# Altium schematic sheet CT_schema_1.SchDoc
size 500 x 441 mm
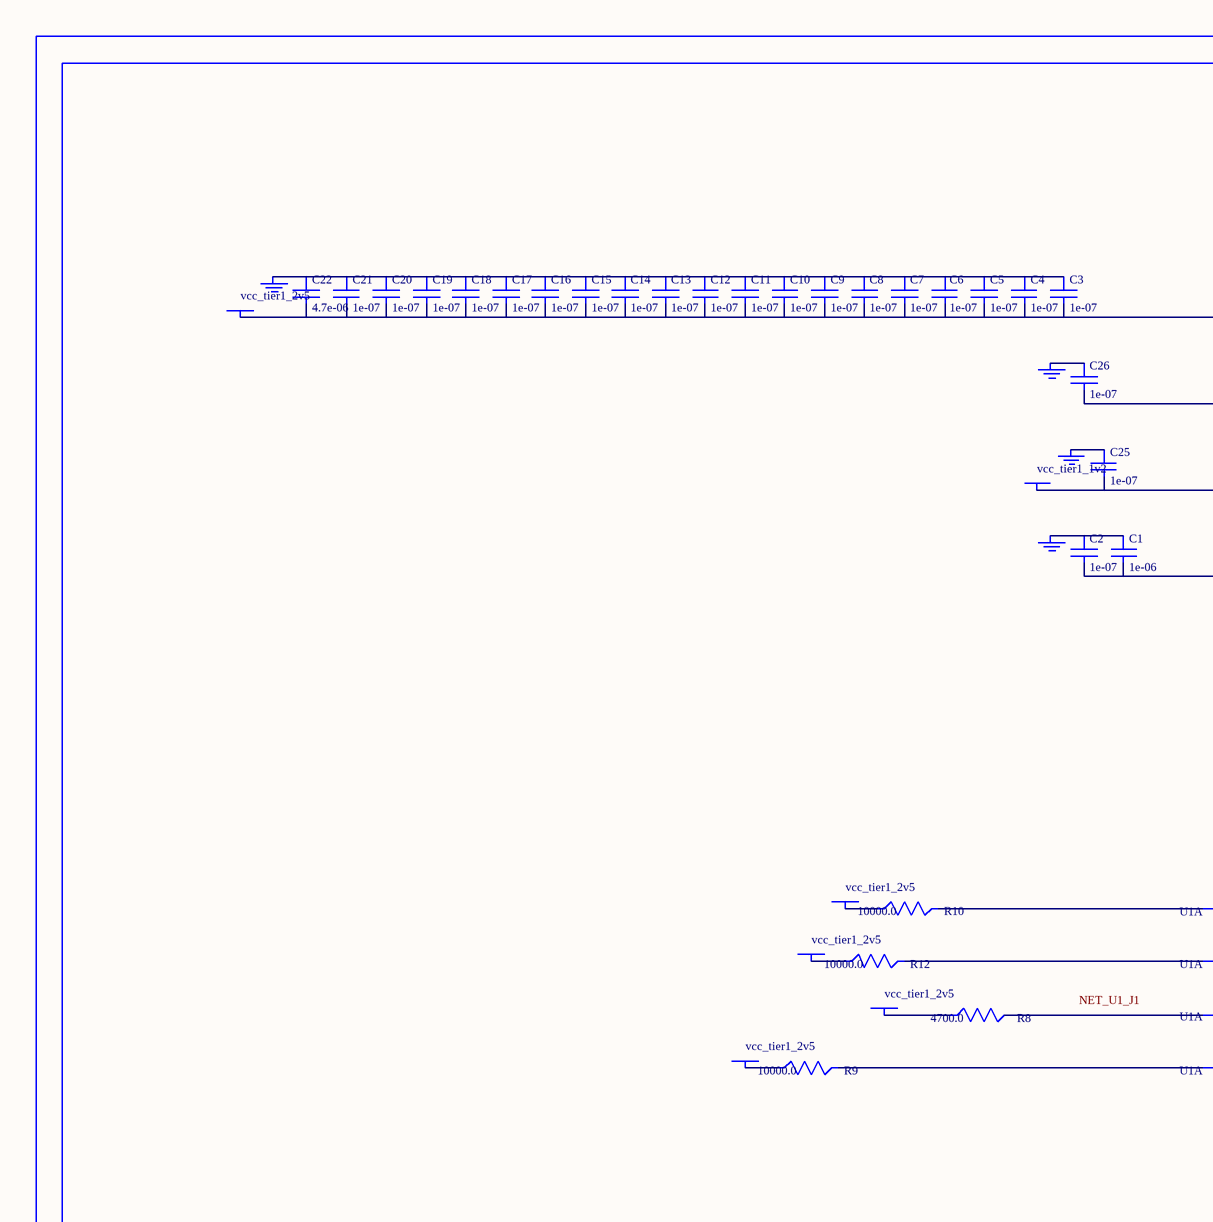
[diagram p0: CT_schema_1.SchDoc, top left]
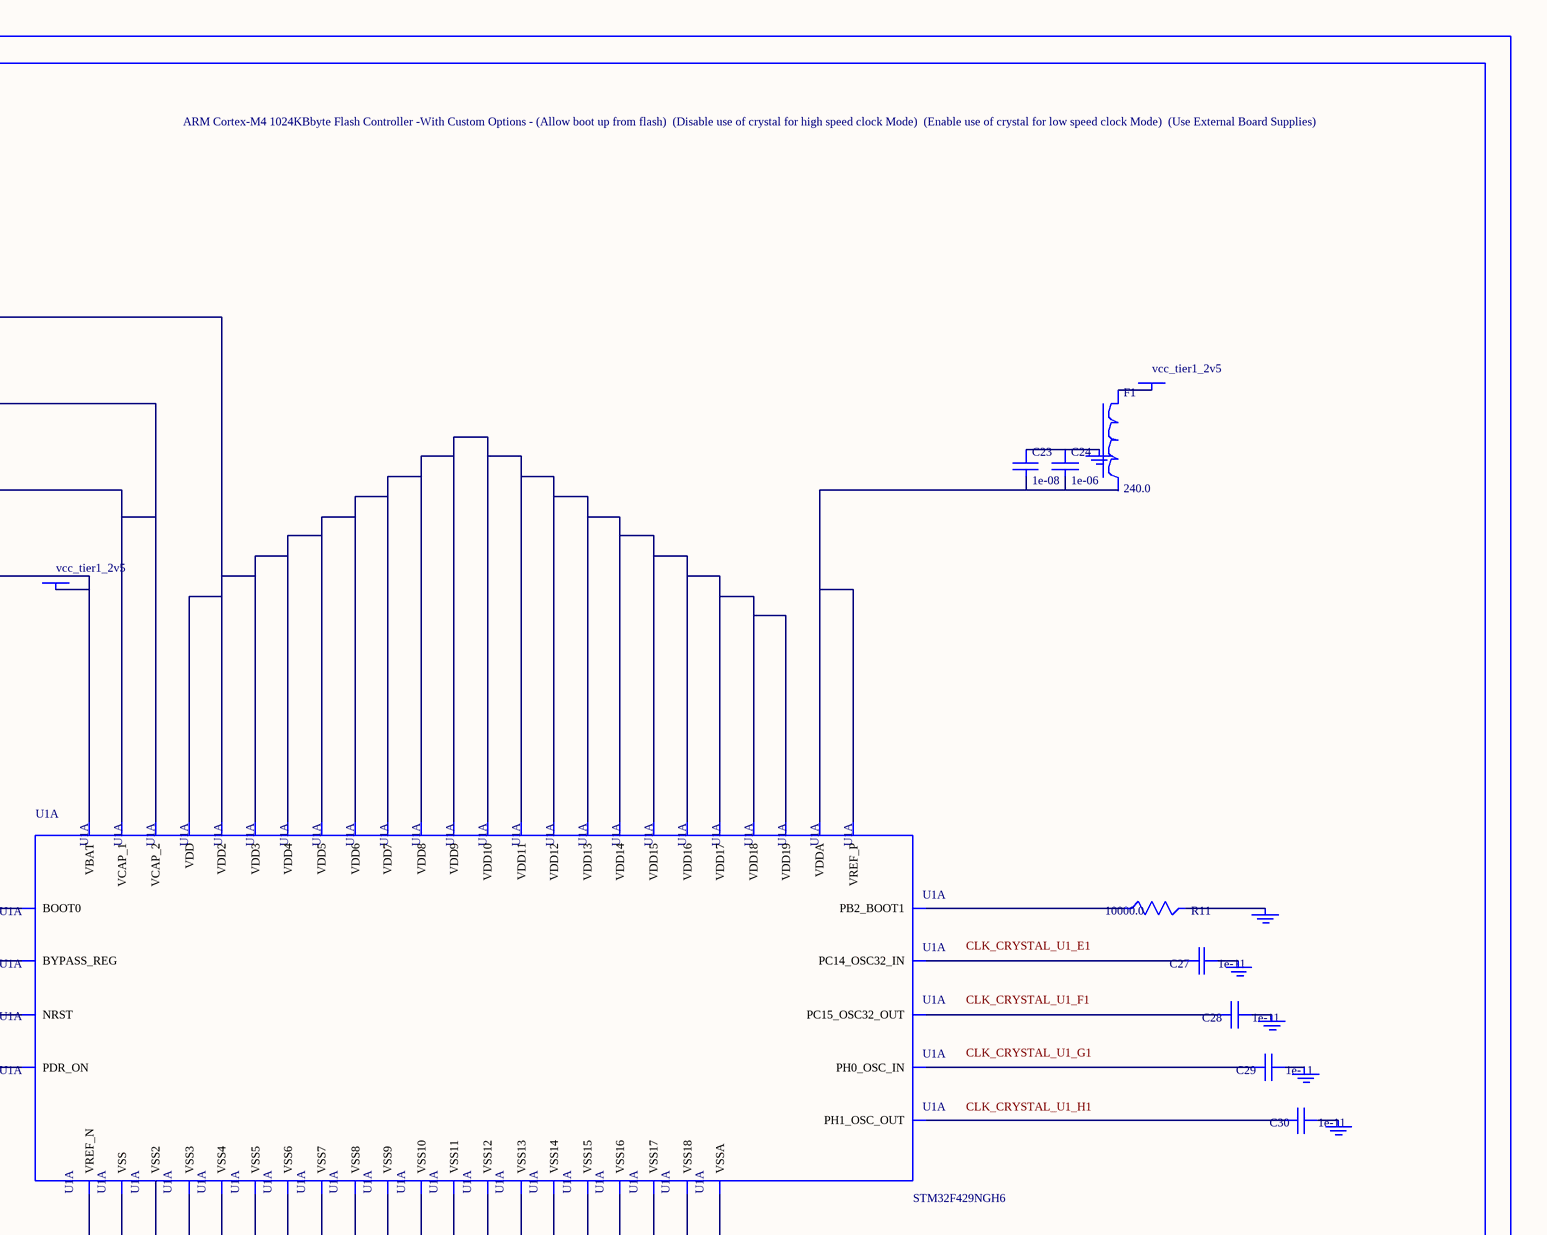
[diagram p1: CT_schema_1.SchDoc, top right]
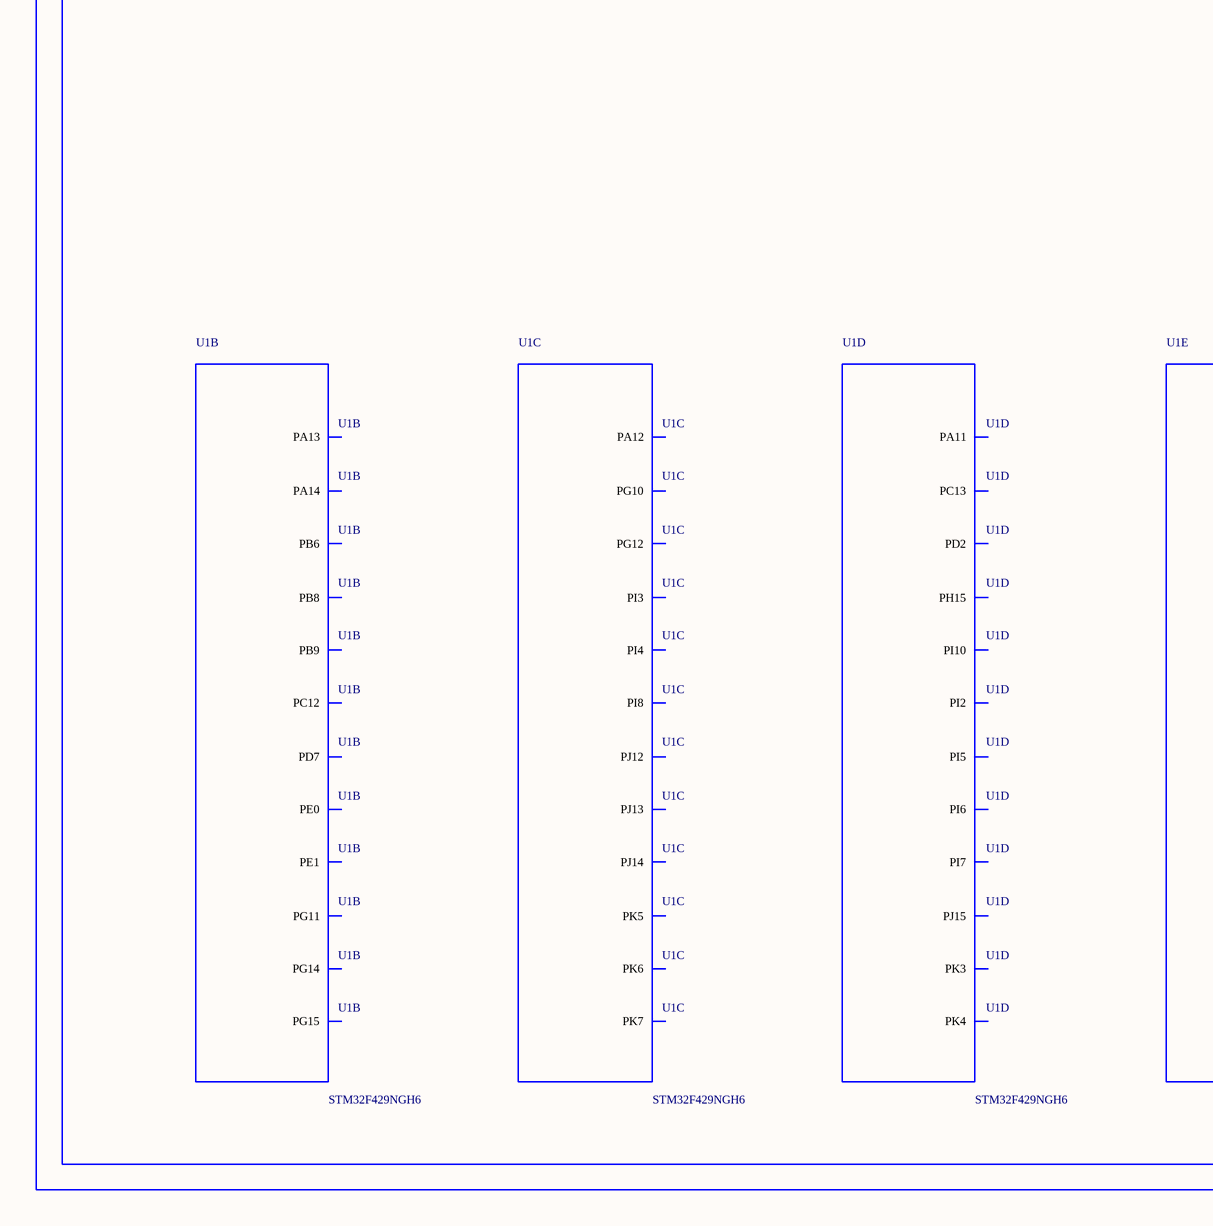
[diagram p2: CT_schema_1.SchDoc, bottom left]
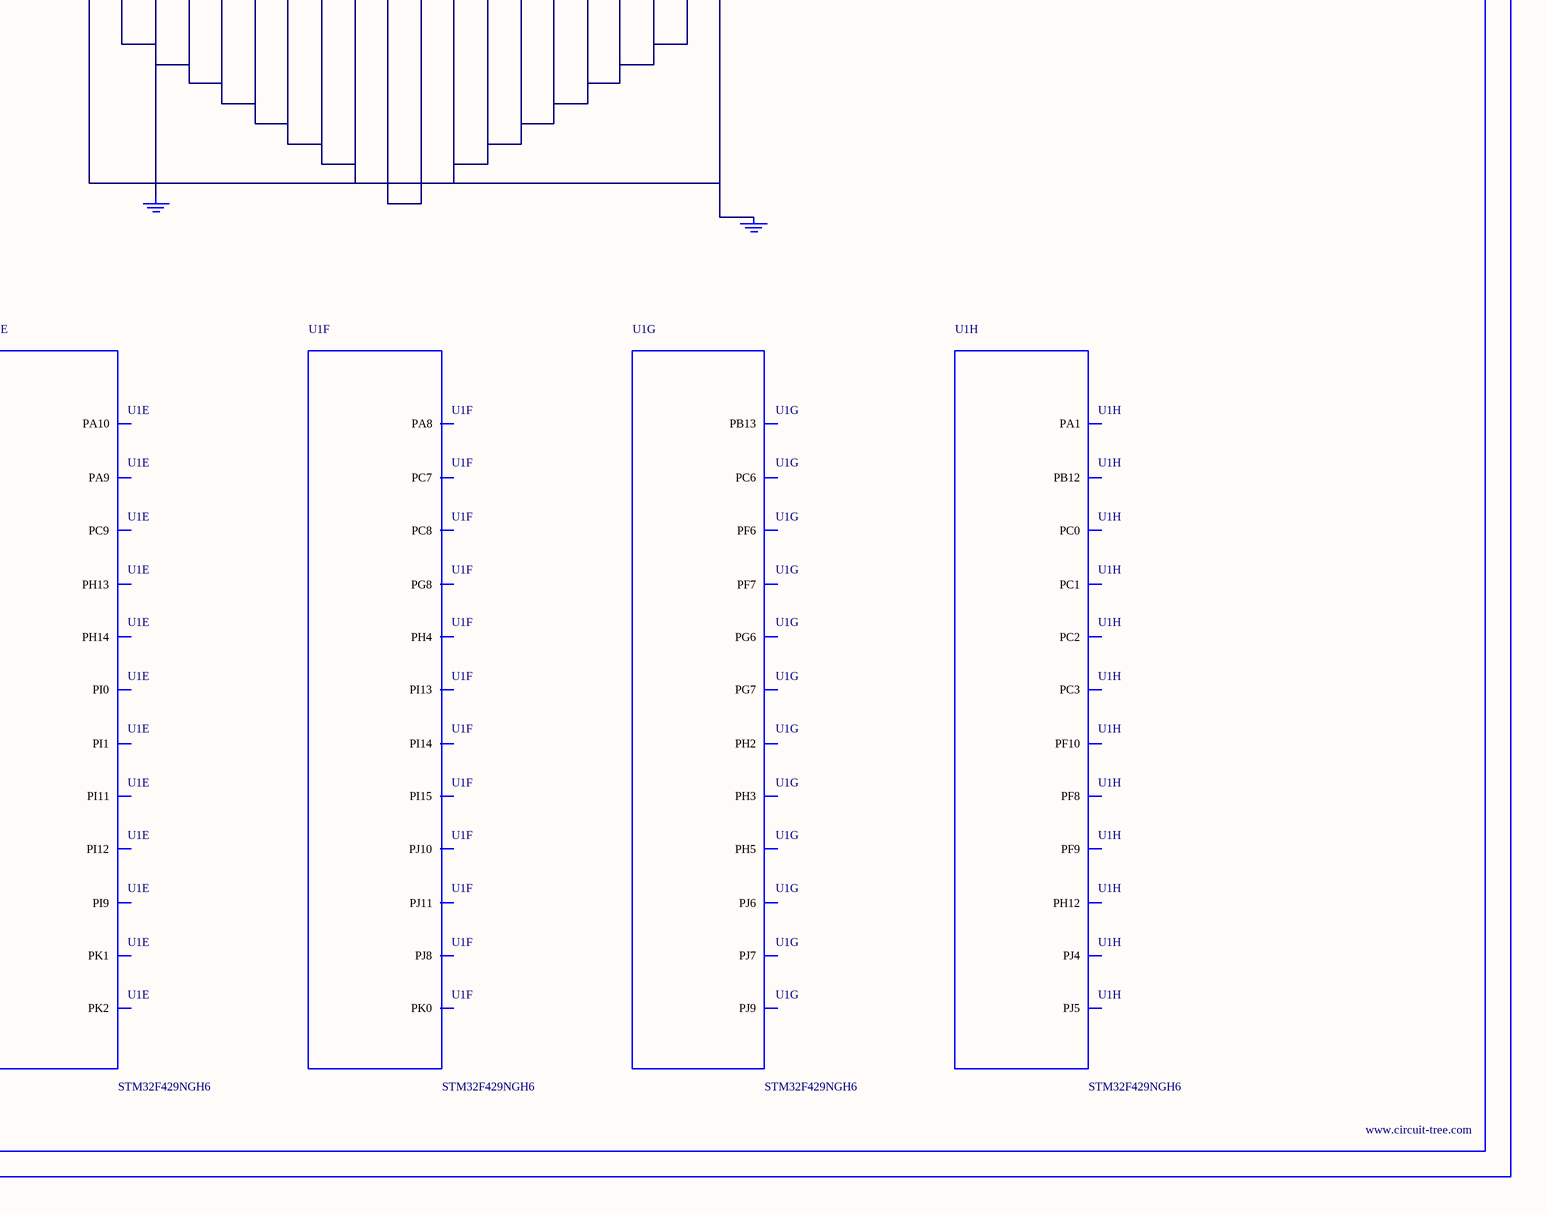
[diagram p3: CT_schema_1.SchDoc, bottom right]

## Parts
BORDER0  (no value)
C1  1e-06  [C0603]
C2  1e-07  [C0603]
C3  1e-07  [C0603]
C4  1e-07  [C0603]
C5  1e-07  [C0603]
C6  1e-07  [C0603]
C7  1e-07  [C0603]
C8  1e-07  [C0603]
C9  1e-07  [C0603]
C10  1e-07  [C0603]
C11  1e-07  [C0603]
C12  1e-07  [C0603]
C13  1e-07  [C0603]
C14  1e-07  [C0603]
C15  1e-07  [C0603]
C16  1e-07  [C0603]
C17  1e-07  [C0603]
C18  1e-07  [C0603]
C19  1e-07  [C0603]
C20  1e-07  [C0603]
C21  1e-07  [C0603]
C22  4.7e-06  [C0603]
C23  1e-08  [C0603]
C24  1e-06  [C0603]
C25  1e-07  [C0402]
C26  1e-07  [C0402]
C27  1e-11  [C0402]
C28  1e-11  [C0402]
C29  1e-11  [C0402]
C30  1e-11  [C0402]
F1  240.0  [L0603]
GND_INSTANCE_0_0  (no value)
GND_INSTANCE_0_1  (no value)
GND_INSTANCE_0_2  (no value)
GND_INSTANCE_0_3  (no value)
GND_INSTANCE_0_4  (no value)
GND_INSTANCE_0_5  (no value)
GND_INSTANCE_0_6  (no value)
GND_INSTANCE_0_7  (no value)
GND_INSTANCE_0_8  (no value)
GND_INSTANCE_0_9  (no value)
GND_INSTANCE_0_10  (no value)
GND_INSTANCE_0_11  (no value)
POWER_INSTANCE_0_0  vcc_tier1_2v5
POWER_INSTANCE_0_1  vcc_tier1_2v5
POWER_INSTANCE_0_2  vcc_tier1_2v5
POWER_INSTANCE_0_3  vcc_tier1_2v5
POWER_INSTANCE_0_4  vcc_tier1_2v5
POWER_INSTANCE_0_5  vcc_tier1_2v5
POWER_INSTANCE_0_6  vcc_tier1_1v2
POWER_INSTANCE_0_7  vcc_tier1_2v5
R8  4700.0  [R0603]
R9  10000.0  [R0603]
R10  10000.0  [R0603]
R11  10000.0  [R0603]
R12  10000.0  [R0603]
U1  STM32F429NGH6  [TFBGA216]  (parts A,B,C,D,E,F,G,H of 16)

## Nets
NetC1_1: C1.1 C2.1 GND_INSTANCE_0_0.0(GND)
NetC1_2: C1.2 C2.2 POWER_INSTANCE_0_0.0(PWR) U1.C1(VBAT)
NetC3_1: C3.1 C4.1 C5.1 C6.1 C7.1 C8.1 C9.1 C10.1 C11.1 C12.1 C13.1 C14.1 C15.1 C16.1 C17.1 C18.1 C19.1 C20.1 C21.1 C22.1 GND_INSTANCE_0_2.0(GND)
NetC3_2: C3.2 C4.2 C5.2 C6.2 C7.2 C8.2 C9.2 C10.2 C11.2 C12.2 C13.2 C14.2 C15.2 C16.2 C17.2 C18.2 C19.2 C20.2 C21.2 C22.2 POWER_INSTANCE_0_2.0(PWR) U1.E7(VDD2) U1.E8(VDD3) U1.E9(VDD4) U1.E10(VDD) U1.F4(VDD6) U1.F5(VDD7) U1.F11(VDD5) U1.G5(VDD9) U1.G11(VDD8) U1.H5(VDD11) U1.H11(VDD10) U1.J5(VDD13) U1.J11(VDD12) U1.K5(VDD15) U1.K11(VDD14) U1.L7(VDD17) U1.L8(VDD18) U1.L9(VDD19) U1.L10(VDD16)
NetC23_1: C23.1 C24.1 GND_INSTANCE_0_1.0(GND)
NetC23_2: C23.2 C24.2 U1.P1(VREF_P) U1.R1(VDDA)
NetC25_1: C25.1 GND_INSTANCE_0_4.0(GND)
NetC25_2: C25.2 C26.2 POWER_INSTANCE_0_6.0(PWR) U1.E11(VCAP_2) U1.L11(VCAP_1)
NetC26_1: C26.1 GND_INSTANCE_0_5.0(GND)
NetC27_1: C27.1 GND_INSTANCE_0_6.0(GND)
NetC27_2: C27.2 U1.E1(PC14_OSC32_IN)
NetC28_1: C28.1 GND_INSTANCE_0_7.0(GND)
NetC28_2: C28.2 U1.F1(PC15_OSC32_OUT)
NetC29_1: C29.1 GND_INSTANCE_0_8.0(GND)
NetC29_2: C29.2 U1.G1(PH0_OSC_IN)
NetC30_1: C30.1 GND_INSTANCE_0_9.0(GND)
NetC30_2: C30.2 U1.H1(PH1_OSC_OUT)
NetF1_1: F1.1 POWER_INSTANCE_0_1.0(PWR)
NetGND_INSTANCE_0_3_0: GND_INSTANCE_0_3.0(GND) R11.2
NetGND_INSTANCE_0_10_0: GND_INSTANCE_0_10.0(GND) GND_INSTANCE_0_11.0(GND) U1.F2(VSS2) U1.F6(VSS3) U1.F7(VSS4) U1.F8(VSS5) U1.F9(VSS6) U1.F10(VSS) U1.G6(VSS8) U1.G10(VSS7) U1.H6(VSS10) U1.H10(VSS9) U1.J6(VSS12) U1.J10(VSS11) U1.K6(VSS14) U1.K7(VSS15) U1.K8(VSS16) U1.K9(VSS17) U1.K10(VSS13) U1.L6(VSS18) U1.M1(VSSA) U1.N1(VREF_N)
NetPOWER_INSTANCE_0_3_0: POWER_INSTANCE_0_3.0(PWR) R9.1
NetPOWER_INSTANCE_0_4_0: POWER_INSTANCE_0_4.0(PWR) R10.1
NetPOWER_INSTANCE_0_5_0: POWER_INSTANCE_0_5.0(PWR) R12.1
NetPOWER_INSTANCE_0_7_0: POWER_INSTANCE_0_7.0(PWR) R8.1
NetR8_2: R8.2 U1.J1(NRST)
NetR9_2: R9.2 U1.E5(PDR_ON)
NetR10_2: R10.2 U1.E6(BOOT0)
NetR11_1: R11.1 U1.M5(PB2_BOOT1)
NetR12_2: R12.2 U1.L5(BYPASS_REG)

Not connected (* = marked no-connect by the designer): F1 2; U1 A4(PG14) A5(PE1) A6(PE0) A7(PB8) A11(PD7) A12(PC12) A14(PA14) A15(PA13) B4(PB9) B6(PB6) B7(PG15) B8(PG11) B9(PJ13) B10(PJ12) B15(PA12) C2(PI8) C3(PI4) C4(PK7) C5(PK6) C6(PK5) C7(PG12) C8(PG10) C9(PJ14) C13(PI3) C14(PI2) C15(PA11) D1(PC13) D3(PI5) D4(PI7) D5(PI10) D6(PI6) D7(PK4) D8(PK3) D10(PJ15) D12(PD2) D13(PH15) D14(PI1) D15(PA10) E3(PI12) E4(PI9) E12(PH13) E13(PH14) E14(PI0) E15(PA9) F3(PI11) F12(PK1) F13(PK2) F14(PC9) F15(PA8) G3(PI13) G4(PI15) G12(PJ11) G13(PK0) G14(PC8) G15(PC7) H3(PI14) H4(PH4) H12(PJ8) H13(PJ10) H14(PG8) H15(PC6) J3(PH5) J4(PH3) J12(PJ7) J13(PJ9) J14(PG7) J15(PG6) K1(PF7) K2(PF6) K4(PH2) K12(PJ6) K14(PB13) L1(PF10) L2(PF9) L3(PF8) L4(PC3) L13(PB12) M2(PC0) M3(PC1) M4(PC2) M9(PJ4) M14(PJ5) M15(PH12) N2(PA1)

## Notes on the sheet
- Labels drawn without touching a wire or pin: CLK_CRYSTAL_U1_E1, CLK_CRYSTAL_U1_F1, CLK_CRYSTAL_U1_G1, CLK_CRYSTAL_U1_H1, NET_U1_J1

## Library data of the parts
BORDER0 = BORDER_PAGE0
C1 C24 = C0603C105K3RACTU
C2-C21 = 06035C104K4Z2A
C22 = GRM188R6YA475KE15D
C23 = 06035C103K4Z2A
C25 C26 = C0402C104K3RACTU
C27-C30 = C0402C100K3GACTU
F1 = Z0603C241ASMST
GND_INSTANCE_0_0-GND_INSTANCE_0_11 = GND
POWER_INSTANCE_0_0-POWER_INSTANCE_0_7 = PWR
R8 = RC0603JR-074K7L
R9-R12 = RC0603JR-0710KL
